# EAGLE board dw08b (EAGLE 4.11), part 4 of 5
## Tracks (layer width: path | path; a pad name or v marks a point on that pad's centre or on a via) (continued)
P_AC02  (via drill 0.61) (continued)
  Bottom 0.305: v95,52.07 93.47,52.07 93.22,52.32 91.19,52.32 B18.E1 | v95.25,48.01 99.31,48.01 99.57,47.75 100.33,47.75 100.58,48.01 102.11,48.01 103.38,49.28 105.66,49.28 B16.F2
P_AC03  (via drill 0.61)
  Top 0.305: v88.65,65.53 88.65,63.5 88.9,63.25 88.9,60.2 88.65,59.94 88.65,57.15 88.9,56.9 88.9,53.85 87.88,52.83 87.88,51.56 90.42,49.02 90.42,46.74 B18.H1
  2 0.305: v88.65,65.53 88.65,67.82 78.23,78.23 78.23,79.25 41.15,116.33 40.39,116.33 A22.H1
  Bottom 0.305: B16.H2 108.97,45.97 105.66,45.97 104.39,44.7 95.25,44.7 93.98,45.97 91.19,45.97 B18.H1
P_AC04  (via drill 0.61)
  Top 0.305: v84.33,81.28 84.07,81.03 v84.07,70.87 | v104.14,48.01 105.66,48.01 105.66,47.5 106.43,46.74 106.43,43.43 B16.J2
  2 0.305: v84.07,70.87 84.07,68.58 88.65,64.01 88.65,63.5 88.9,63.25 88.9,60.2 88.39,59.69 88.65,59.44 88.65,58.67 90.42,56.9 91.95,56.9 92.46,57.4 92.71,57.15 95,57.15 v104.14,48.01
  15 0.305: v51.82,111.25 50.29,109.73 50.55,109.47 50.55,108.97 64.52,95 66.55,95 67.06,95.5 67.31,95.25 68.58,95.25 69.85,93.98 69.85,91.95 69.34,91.44 69.6,91.19 69.6,89.92 77.22,82.3 79.25,82.3 79.76,82.8 80.01,82.55 82.3,82.55 83.57,81.28 v84.33,81.28
  Bottom 0.305: B18.J1 87.63,42.16 92.46,42.16 93.22,41.4 100.33,41.4 100.58,41.66 101.09,41.66 102.36,42.93 105.66,42.93 B16.J2 | v51.82,111.25 42.42,111.25 40.89,112.78 37.08,112.78 A22.J1
P_AC05  (via drill 0.61)
  Top 0.305: v109.47,43.18 109.47,40.39 B16.K2
  15 0.305: v48.26,107.7 48.51,107.95 50.55,107.95 78.99,79.5 78.99,78.49 90.68,66.8 91.44,66.8 96.27,61.98 96.27,60.96 94.49,59.18 106.68,46.99 106.68,45.97 v109.47,43.18
  Bottom 0.305: B18.L1 87.88,36.58 89.92,36.58 91.19,37.85 91.95,37.85 92.2,38.1 95,38.1 95.25,37.85 98.3,37.85 98.55,38.1 101.35,38.1 101.6,37.85 104.65,37.85 106.43,39.62 108.97,39.62 B16.K2 | v48.26,107.7 44.45,107.7 44.2,107.95 41.4,107.95 41.15,107.7 37.85,107.7 A22.L1
P_AC06  (via drill 0.61)
  Top 0.305: v66.04,80.01 66.04,78.49 66.29,78.23 66.29,73.15 66.04,72.9 66.04,69.6 67.06,68.58 67.06,62.48 66.55,61.98 v66.55,61.72
  2 0.305: v41.4,103.12 41.66,103.12 60.96,83.82 60.96,83.57 61.98,82.55 63.25,82.55 65.02,80.77 65.28,80.77 v66.04,80.01
  15 0.305: v66.55,61.72 80.52,47.75 80.52,45.47 78.99,43.94 78.99,42.42 88.14,33.27 v88.9,33.27
  Bottom 0.305: B16.L2 105.66,36.58 103.38,36.58 102.11,35.31 100.58,35.31 100.33,35.05 95.5,35.05 95,34.54 91.44,34.54 90.93,34.04 B18.M1 89.92,33.27 v88.9,33.27 | v41.4,103.12 40.39,103.12 A22.M1
P_AC07  (via drill 0.61)
  Top 0.305: v90.68,31.5 90.68,29.97 90.42,29.72 90.42,27.69 B18.P1 | v39.62,95.25 39.62,96.27 A22.P1 | v62.23,72.9 62.23,69.6 62.48,69.34 62.48,63.75 v62.23,63.5
  2 0.305: v39.62,95.25 39.62,95 49.53,85.09 49.78,85.09 50.55,84.33 50.55,84.07 55.63,78.99 56.13,78.99 v62.23,72.9 | v59.18,63.25 59.18,61.98 69.09,52.07 69.09,51.82 69.6,51.31 69.6,51.05 89.41,31.24 90.42,31.24 v90.68,31.5
  Bottom 0.305: v90.68,31.5 91.95,31.5 92.2,31.75 95,31.75 95.25,31.5 98.3,31.5 98.55,31.75 101.35,31.75 101.6,31.5 104.65,31.5 106.43,33.27 108.97,33.27 B16.M2 | v62.23,63.5 60.2,63.5 59.94,63.25 v59.18,63.25
P_AC08  (via drill 0.61)
  Top 0.305: v90.68,25.15 90.68,23.62 90.42,23.37 90.42,21.34 B18.S1 | v106.17,25.4 106.17,26.92 106.43,27.18 106.43,29.46 B16.N2 | v64.52,54.1 63.25,52.83 63.25,50.8 63.5,50.55 63.5,47.5 63.25,47.24 v63.25,46.23
  2 0.305: v63.25,46.23 63.25,45.72 77.47,31.5 v77.98,31.5 | v84.07,31.5 84.07,30.99 88.9,26.16 89.41,26.16 90.42,25.15 v90.68,25.15
  15 0.305: v64.52,54.1 64.52,55.37 51.56,68.33 51.56,70.36 45.47,76.45 45.47,82.8 39.12,89.15 39.12,89.92 A22.S1
  Bottom 0.305: v90.68,25.15 91.95,25.15 92.2,25.4 95,25.4 95.25,25.15 98.3,25.15 98.55,25.4 101.35,25.4 101.6,25.15 104.65,25.15 104.9,25.4 v106.17,25.4 | v77.98,31.5 79.25,31.5 79.5,31.75 82.3,31.75 82.55,31.5 v84.07,31.5
P_AC09  (via drill 0.61)
  Top 0.305: v25.4,124.46 25.4,123.7 25.15,123.44 25.15,120.65 25.4,120.4 25.4,117.35 25.15,117.09 25.15,114.3 25.4,114.05 25.4,111 25.15,110.74 25.15,107.95 25.4,107.7 25.4,104.65 25.15,104.39 25.15,101.6 25.4,101.35 v25.4,97.79
  2 0.305: v25.4,97.79 25.15,97.79 24.38,97.03 24.38,96.01 35.31,85.09 37.08,85.09 37.85,84.33 37.85,82.55 38.86,81.53 38.86,80.77 43.69,75.95 46.99,75.95 52.32,70.61 v52.58,70.61
  15 0.305: v105.16,27.43 93.98,38.61 93.98,39.12 88.65,44.45 88.65,45.97 80.52,54.1 80.52,54.86 B18.D2 | v55.88,70.61 56.39,70.61 60.45,66.55 60.45,62.99 59.69,62.23 65.02,56.9 66.55,56.9 67.06,57.4 67.31,57.15 69.6,57.15 v70.87,55.88
  Bottom 0.305: v105.16,27.43 105.41,27.18 106.43,27.18 106.68,26.92 108.97,26.92 B16.P2 | v25.4,124.46 29.46,124.46 29.72,124.71 A22.D2 | v52.58,70.61 v55.88,70.61 | v70.87,55.88 71.88,56.9 72.9,56.9 73.15,57.15 75.95,57.15 77.47,55.63 80.26,55.63 B18.D2
P_AC10  (via drill 0.61)
  Top 0.305: v101.6,23.62 101.6,25.15 101.35,25.4 101.35,28.45 101.6,28.7 101.6,31.5 101.35,31.75 101.35,34.8 101.6,35.05 101.6,37.85 100.58,38.86 v100.58,40.39 | v33.02,117.6 33.27,117.86 33.27,121.67 A22.E2 | v37.85,117.09 37.85,114.3 38.1,114.05 38.1,111 37.85,110.74 37.85,107.95 38.1,107.7 38.1,104.65 37.85,104.39 37.85,101.6 41.66,97.79 41.66,94.23 41.4,93.98 41.4,93.22 41.66,92.96 v41.66,91.44 | v83.57,47.75 84.07,48.26 84.07,51.82 B18.E2
  15 0.305: v100.58,40.39 v88.9,52.07 | v41.66,91.44 41.91,91.44 48.26,85.09 49.78,85.09 50.55,84.33 50.55,84.07 55.63,78.99 56.13,78.99 61.21,73.91 61.21,70.61 65.02,66.8 65.53,66.8 68.83,63.5 68.83,63.25 83.57,48.51 v83.57,47.75
  Bottom 0.305: v101.6,23.62 103.12,23.62 103.38,23.88 105.66,23.88 B16.R2 | v88.9,52.07 88.65,51.82 84.58,51.82 B18.E2 | v33.02,117.6 34.54,117.6 35.05,117.09 v37.85,117.09
P_AC11  (via drill 0.61)
  Top 0.305: v84.33,41.4 84.33,42.93 84.07,43.18 84.07,45.47 B18.H2 | v35.31,101.6 35.31,105.66 35.05,105.92 35.05,110.74 34.54,111.25 34.54,115.06 34.04,115.57 A22.H2
  15 0.305: v84.33,41.4 93.98,31.75 95,31.75 v106.17,20.57 | v35.31,101.6 36.83,101.6 58.42,80.01 58.42,79.25 63.5,74.17 64.01,74.17 66.04,72.14 66.04,67.31 69.6,63.75 69.6,63.5 84.58,48.51 84.58,46.74 B18.H2
  Bottom 0.305: v106.17,20.57 108.97,20.57 B16.S2
P_ACCEPT  (via drill 0.61)
  Top 0.305: v21.84,78.74 21.84,82.04 22.35,82.55 22.35,85.34 21.84,85.85 21.84,89.66 21.34,90.17 A23.S2 | v51.82,78.74 v51.82,75.95 | v133.1,76.2 133.1,63.5 133.35,63.25 133.35,60.2 133.1,59.94 133.1,57.15 133.35,56.9 133.35,53.85 133.1,53.59 133.1,50.8 133.35,50.55 133.35,47.5 133.1,47.24 133.1,44.45 133.35,44.2 133.35,41.15 132.08,39.88 132.08,39.37 131.83,39.12 131.83,37.08 B14.L2 | v127,19.05 126.75,19.3 126.75,22.1 127,22.35 127,25.15 126.75,25.4 126.75,28.45 127,28.7 127,31.5 126.75,31.75 126.75,34.8 127,35.05 v127,36.32
  Bottom 0.305: v21.84,78.74 v51.82,78.74 | v51.82,75.95 52.07,76.2 56.39,76.2 56.64,76.45 69.09,76.45 69.34,76.2 72.14,76.2 72.64,76.71 79.5,76.71 79.76,76.45 92.71,76.45 92.96,76.2 94.49,76.2 95,76.71 100.58,76.71 100.84,76.45 119.89,76.45 120.14,76.2 v133.1,76.2 | v127,19.05 123.95,19.05 122.43,17.53 119.63,17.53 B15.T2 | v127,36.32 128.52,36.32 128.78,36.58 131.06,36.58 B14.L2
P_ACCLR  (via drill 0.61)
  Top 0.305: v82.55,26.92 82.55,31.5 82.3,31.75 82.3,34.8 82.55,35.05 82.55,37.85 82.3,38.1 82.3,41.15 82.55,41.4 v82.55,44.2 | v93.47,44.45 93.47,45.97 93.73,46.23 93.73,48.51 B17.F2 | v33.27,92.2 33.27,96.27 A22.P2 | v44.45,71.37 v44.45,82.3 | v79.5,70.87 79.5,55.12 79.76,54.86 79.76,49.78 79.5,49.53 v79.5,46.99
  2 0.305: v44.45,82.3 v35.05,91.69 | v79.5,46.99 82.3,44.2 v82.55,44.2
  Bottom 0.305: v82.55,26.92 83.57,26.92 B18.P2 | v82.55,44.2 85.6,44.2 85.85,44.45 88.65,44.45 88.9,44.2 91.95,44.2 92.2,44.45 v93.47,44.45 | v33.27,92.2 34.54,92.2 v35.05,91.69 | v44.45,71.37 44.7,71.63 50.8,71.63 51.05,71.88 56.13,71.88 56.9,71.12 63.75,71.12 64.26,70.61 79.25,70.61 v79.5,70.87
P_ADD00  (via drill 0.61)
  Top 0.305: v69.6,72.14 69.6,63.5 69.85,63.25 69.85,60.45 68.33,58.93 68.33,56.13 B19.D2 | v98.3,72.39 98.04,72.64 98.04,82.3 98.55,82.8 98.55,83.82 98.81,84.07 98.81,86.61 98.55,86.87 v98.55,90.42 | v23.88,130.05 23.88,131.06 A23.B1 | v53.85,99.82 54.36,99.31 54.36,94.23 54.1,93.98 54.1,82.55 53.59,82.04 v53.59,78.99 | v67.06,72.39 v67.06,78.99
  15 0.305: v23.88,130.05 23.88,129.79 27.69,125.98 27.69,125.48 53.34,99.82 v53.85,99.82
  Bottom 0.305: v98.3,72.39 91.69,72.39 91.44,72.64 78.49,72.64 78.23,72.9 73.91,72.9 73.41,72.39 69.85,72.39 v69.6,72.14 69.34,72.39 v67.06,72.39 | v98.55,90.42 102.62,90.42 A17.S1 | v53.59,78.99 56.13,78.99 56.39,78.74 66.8,78.74 v67.06,78.99
P_ADD01  (via drill 0.61)
  Top 0.305: v25.4,130.3 25.4,130.05 23.88,128.52 23.88,125.98 A23.D1 23.88,124.71 v23.88,123.44 | v41.15,130.3 40.89,130.56 40.89,133.1 v43.18,135.38 | v69.09,79.5 69.09,77.47 73.15,73.41 73.15,57.4 72.64,56.9 72.64,53.34 72.14,52.83 B19.E2
  2 0.305: v69.09,79.5 70.36,80.77 68.58,82.55 66.55,82.55 66.04,82.04 65.79,82.3 65.02,82.3 62.99,84.33 62.99,84.58 62.48,85.09 60.71,85.09 44.2,101.6 44.2,104.65 44.7,105.16 44.45,105.41 44.45,106.68 43.18,107.95 41.15,107.95 40.64,107.44 40.39,107.7 39.62,107.7 v23.88,123.44
  15 0.305: v43.18,135.38 46.99,139.19 47.24,138.94 50.55,138.94 54.36,142.75 72.39,142.75 84.33,130.81 84.33,130.56 v89.41,125.48
  Bottom 0.305: v25.4,130.3 27.94,130.3 28.45,129.79 31.5,129.79 32,130.3 34.29,130.3 34.8,129.79 37.85,129.79 38.35,130.3 v41.15,130.3 | v89.41,125.48 92.96,125.48 A17.D2
P_ADD02  (via drill 0.61)
  Top 0.305: v68.33,51.05 68.33,49.78 B19.F2 | v45.47,74.93 45.21,75.18 45.21,81.53 45.47,81.79 45.47,82.8 44.7,83.57 44.7,88.39 44.2,88.9 44.2,91.95 44.45,92.2 44.45,95 44.2,95.25 44.2,98.3 44.45,98.55 44.45,101.35 44.2,101.6 44.2,104.65 44.45,104.9 44.45,107.7 44.2,107.95 44.2,111 44.45,111.25 44.45,114.05 44.2,114.3 44.2,117.35 44.45,117.6 v44.45,120.9
  2 0.305: v68.33,51.05 68.33,51.82 57.15,62.99 57.15,63.25 v45.47,74.93
  Bottom 0.305: A17.E2 96.27,122.17 92.46,122.17 91.19,120.9 v44.45,120.9 31.75,120.9 30.48,122.17 27.69,122.17 A23.E1
P_ADD03  (via drill 0.61)
  Top 0.305: v75.95,46.23 75.95,47.5 76.2,47.75 76.2,50.55 75.95,50.8 75.95,53.85 76.2,54.1 76.2,56.9 75.95,57.15 75.95,59.18 76.96,60.2 76.96,62.48 77.22,62.74 77.22,63.75 75.95,65.02 75.95,78.99 76.2,79.25 76.2,82.3 75.95,82.55 75.95,85.6 76.2,85.85 76.2,88.65 75.95,88.9 75.95,91.95 76.2,92.2 76.2,95 75.95,95.25 75.95,98.3 76.2,98.55 76.2,101.35 75.95,101.6 75.95,104.65 76.2,104.9 76.2,107.7 75.95,107.95 75.95,111 76.2,111.25 v76.2,114.55
  Bottom 0.305: A17.H2 96.27,115.82 92.46,115.82 91.19,114.55 v76.2,114.55 31.75,114.55 30.48,115.82 27.69,115.82 A23.H1 | v75.95,46.23 74.42,46.23 74.17,45.97 72.14,45.97 B19.H2
P_ADD04  (via drill 0.61)  (1 unrouted)
  Top 0.305: v60.45,52.32 60.45,66.55 59.94,67.06 59.94,70.1 58.42,71.63 58.42,72.64 58.67,72.9 58.67,78.99 57.15,80.52 57.15,82.3 56.9,82.55 56.9,85.6 57.15,85.85 57.15,88.65 56.9,88.9 56.9,91.95 57.15,92.2 v57.15,93.47
  15 0.305: v60.45,52.32 60.96,52.32 68.83,44.45 68.83,43.43 B19.J2 | v57.15,93.47 57.15,93.98 39.88,111.25 v39.37,111.25
  Bottom 0.305: v39.37,111.25 29.72,111.25 28.19,112.78 24.38,112.78 A23.J1
P_ADD05  (via drill 0.61)  (1 unrouted)
  Top 0.305: v71.12,43.18 71.37,42.93 71.37,40.39 B19.K2 | v21.84,93.98 21.84,94.74 22.61,95.5 22.61,99.31 22.35,99.57 22.35,100.33 22.61,100.58 22.61,102.11 23.88,103.38 23.88,105.66 A23.L1
  15 0.305: v71.12,43.18 46.99,67.31 46.99,67.56 44.7,69.85 42.42,69.85 35.56,76.71 35.56,78.23 21.84,91.95 v21.84,93.98
P_ADD06  (via drill 0.61)
  Top 0.305: v50.55,39.62 50.55,38.1 50.8,37.85 v50.8,35.31 | v28.19,71.88 28.19,82.04 28.7,82.55 28.7,93.98 28.96,94.23 28.96,97.79 28.19,98.55 28.19,102.36 27.69,102.87 A23.M1 | v31.5,71.88 31.5,63.5 31.75,63.25 31.75,60.2 31.5,59.94 31.5,57.15 31.75,56.9 31.75,53.85 31.5,53.59 31.5,50.8 31.75,50.55 31.75,47.5 31.5,47.24 31.5,44.45 31.75,44.2 v31.75,41.66
  Bottom 0.305: v50.55,39.62 46.74,39.62 B21.K2 45.47,39.62 42.67,39.62 40.89,41.4 36.07,41.4 35.81,41.66 v31.75,41.66 | v50.8,35.31 54.86,35.31 55.12,35.05 62.23,35.05 62.48,35.31 64.01,35.31 65.28,36.58 67.56,36.58 B19.L2 | v31.5,71.88 v28.19,71.88
P_ADD07  (via drill 0.61)
  Top 0.305: v26.92,95.25 26.92,96.27 A23.P1 | v38.1,95.25 38.1,91.95 37.85,91.69 37.85,88.9 38.1,88.65 38.1,85.6 37.85,85.34 37.85,82.55 38.1,82.3 38.1,66.8 37.85,66.55 37.85,63.5 38.1,63.25 38.1,60.2 37.85,59.94 37.85,57.15 38.1,56.9 38.1,53.85 37.85,53.59 37.85,50.8 38.1,50.55 38.1,47.5 37.85,47.24 37.85,44.45 38.1,44.2 38.1,41.15 37.85,40.89 37.85,38.1 38.1,37.85 v38.1,35.05
  Bottom 0.305: B19.M2 70.87,33.27 67.56,33.27 66.29,32 50.8,32 49.53,33.27 46.74,33.27 B21.M2 45.47,33.27 42.67,33.27 40.89,35.05 v38.1,35.05 | v26.92,95.25 31.5,95.25 31.75,95 34.8,95 35.05,95.25 v38.1,95.25
P_ADD08  (via drill 0.61)
  Top 0.305: v31.5,90.42 31.5,88.9 32,88.39 32,83.57 32.26,83.31 32.26,82.8 32.51,82.55 32.51,74.68 33.02,74.17 v33.02,72.14 | v56.9,72.64 56.9,63.5 57.15,63.25 57.15,60.2 56.9,59.94 56.9,57.15 57.15,56.9 57.15,53.85 56.9,53.59 56.9,50.8 57.15,50.55 57.15,47.5 56.9,47.24 56.9,44.45 57.15,44.2 57.15,41.15 56.9,40.89 56.9,38.1 57.15,37.85 57.15,34.8 56.9,34.54 56.9,31.75 57.15,31.5 v57.15,28.7
  Bottom 0.305: B21.P2 46.48,27.69 46.99,28.19 50.55,28.19 51.05,28.7 v57.15,28.7 62.23,28.7 62.48,28.96 64.01,28.96 65.28,30.23 67.56,30.23 B19.N2 | v31.5,90.42 27.69,90.42 A23.S1 | v33.02,72.14 33.27,72.39 50.55,72.39 50.8,72.64 v56.9,72.64
P_ADD09  (via drill 0.61)
  Top 0.305: v46.23,25.4 46.23,23.62 45.97,23.37 45.97,21.34 B21.S2 | v17.78,120.65 17.53,120.9 17.53,124.71 A23.D2 | v22.86,110.74 22.61,110.49 22.61,106.93 22.35,106.68 22.35,102.87 21.84,102.36 21.84,100.84 21.59,100.58 21.59,100.08 v20.07,98.55 | v8.89,92.2 v8.89,95.25 | v20.83,80.01 20.83,75.69 21.08,75.44 v21.08,67.56 | v25.15,67.56 25.15,63.5 25.4,63.25 25.4,60.2 25.15,59.94 25.15,57.15 25.4,56.9 25.4,53.85 25.15,53.59 25.15,50.8 25.4,50.55 25.4,47.5 25.15,47.24 25.15,44.45 25.4,44.2 25.4,41.15 25.15,40.89 25.15,38.1 25.4,37.85 25.4,34.8 25.15,34.54 25.15,31.75 25.4,31.5 25.4,28.45 25.15,28.19 v25.15,25.4
  2 0.305: v8.89,92.2 9.4,92.2 18.8,82.8 18.8,82.55 19.05,82.3 19.05,81.79 v20.83,80.01
  15 0.305: v26.67,111.76 v17.78,120.65
  Bottom 0.305: B19.P2 70.87,26.92 68.33,26.92 66.55,25.15 63.5,25.15 63.25,25.4 60.45,25.4 60.2,25.15 57.15,25.15 56.9,25.4 54.1,25.4 53.85,25.15 50.8,25.15 50.55,25.4 47.75,25.4 47.5,25.15 46.48,25.15 v46.23,25.4 45.97,25.15 44.45,25.15 44.2,25.4 41.4,25.4 41.15,25.15 38.1,25.15 37.85,25.4 35.05,25.4 34.8,25.15 31.75,25.15 31.5,25.4 28.7,25.4 28.45,25.15 25.4,25.15 v25.15,25.4 | v26.67,111.76 26.16,111.25 25.4,111.25 24.89,110.74 v22.86,110.74 | v20.07,98.55 19.05,98.55 15.49,95 12.7,95 12.45,95.25 v8.89,95.25 | v21.08,67.56 21.34,67.82 24.89,67.82 v25.15,67.56
P_ADD10  (via drill 0.61)
  Top 0.305: v68.33,19.05 68.33,23.11 B19.R2 | v20.57,120.65 20.57,121.67 A23.E2 | v11.43,114.3 v11.43,117.09 | v8.13,111.25 v8.13,114.05 | v12.45,103.12 12.45,101.6 12.7,101.35 v12.7,98.04 | v22.35,75.95 21.84,75.44 21.84,68.33 22.35,67.82 v22.35,51.82 | v44.45,31.5 44.45,28.45 44.2,28.19 44.2,25.4 44.45,25.15 44.45,22.1 42.93,20.57 42.93,18.03 B21.T2
  2 0.305: v8.13,111.25 9.65,109.73 9.65,107.95 8.89,107.19 9.14,106.93 9.14,106.43 v12.45,103.12 | v44.45,31.5 v24.13,51.82
  15 0.305: v20.57,120.65 20.57,120.4 v23.62,117.35 | v12.7,98.04 12.45,98.04 11.68,97.28 11.68,96.01 19.05,88.65 19.05,85.6 18.54,85.09 18.8,84.84 18.8,82.55 19.05,82.3 19.05,79.25 v22.35,75.95
  Bottom 0.305: v68.33,19.05 66.8,19.05 66.55,18.8 63.5,18.8 63.25,19.05 60.45,19.05 60.2,18.8 57.15,18.8 56.9,19.05 54.1,19.05 53.85,18.8 50.8,18.8 50.55,19.05 47.75,19.05 46.23,17.53 43.43,17.53 B21.T2 | v23.62,117.35 23.11,117.86 18.03,117.86 17.78,117.6 12.7,117.6 12.19,117.09 v11.43,117.09 | v11.43,114.3 9.4,114.3 9.14,114.05 v8.13,114.05 | v24.13,51.82 v22.35,51.82
P_ADD11  (via drill 0.61)
  Top 0.305: v42.93,9.14 42.93,10.41 B21.V2 | v69.85,9.14 69.85,12.45 69.6,12.7 69.6,15.75 71.37,17.53 71.37,20.07 B19.S2 | v20.57,111.25 20.57,115.32 A23.H2 | v13.72,80.77 13.97,80.52 13.97,72.14 13.72,71.88 13.72,69.09 12.45,67.82 12.45,63.5 12.7,63.25 12.7,60.2 12.45,59.94 12.45,57.15 12.7,56.9 12.7,53.85 12.45,53.59 12.45,50.8 12.7,50.55 12.7,47.5 12.45,47.24 12.45,44.45 12.7,44.2 12.7,41.15 12.45,40.89 12.45,38.1 12.7,37.85 12.7,34.8 12.45,34.54 12.45,31.75 12.7,31.5 12.7,28.45 12.45,28.19 12.45,25.4 12.7,25.15 12.7,22.1 12.45,21.84 12.45,19.05 12.7,18.8 12.7,15.75 12.45,15.49 12.45,12.7 12.7,12.45 v12.7,7.11
  2 0.305: v11.43,110.49 14.48,107.44 14.73,107.44 15.49,106.68 15.49,106.17 18.8,102.87 18.8,101.6 23.62,96.77 23.62,95.76 26.42,92.96 v26.42,92.2
  Bottom 0.305: v69.85,9.14 v42.93,9.14 42.67,8.89 34.54,8.89 32.77,7.11 31.5,7.11 31.24,6.86 12.95,6.86 v12.7,7.11 | v20.57,111.25 12.7,111.25 11.94,110.49 v11.43,110.49 | v26.42,92.2 25.65,92.2 15.49,82.04 15.49,80.77 v13.72,80.77
P_BAC00  (via drill 0.61)
  15 0.305: v66.55,131.57 66.29,131.32 76.45,121.16 76.96,121.16 77.72,120.4 77.72,119.13 77.47,118.87 77.47,117.86 77.98,117.35 78.23,117.35 81.28,114.3 82.3,114.3 92.46,104.14 92.71,104.14 114.05,82.8 114.05,82.55 117.09,79.5 117.09,76.45 123.19,70.36 123.19,68.58 134.87,56.9 v135.38,56.9
  Bottom 0.305: B12.D2 156.46,55.63 152.65,55.63 151.38,56.9 v135.38,56.9 130.05,56.9 128.78,55.63 125.98,55.63 B15.D1 | v66.55,131.57 66.29,131.83 62.48,131.83 A20.B1
P_BAC01  (via drill 0.61)
  Top 0.305: v156.97,44.45 156.97,45.97 157.23,46.23 157.23,48.51 B12.F2 | v128.52,56.9 128.52,53.09 B15.E1
  2 0.305: v66.04,124.71 75.18,115.57 75.18,114.05 77.98,111.25 79.25,111.25 80.01,110.49 80.26,110.49 85.34,105.41 85.34,105.16 87.88,102.62 87.88,102.36 92.46,97.79 92.71,97.79 107.7,82.8 107.7,82.55 110.74,79.5 110.74,78.49 120.4,68.83 120.4,65.02 v128.52,56.9
  15 0.305: v130.81,53.09 v138.43,45.47
  Bottom 0.305: v130.81,53.09 129.03,53.09 B15.E1 | v138.43,45.47 138.68,45.21 139.7,45.21 140.72,44.2 142.75,44.2 143,44.45 145.8,44.45 146.05,44.2 149.1,44.2 149.35,44.45 152.15,44.45 152.4,44.2 155.45,44.2 155.7,44.45 v156.97,44.45 | v66.04,124.71 65.79,124.46 62.48,124.46 62.23,124.71 A20.D1
P_BAC02  (via drill 0.61)
  Top 0.305: v152.15,47.24 152.15,44.45 152.4,44.2 v152.4,42.93 | v134.87,62.23 135.13,61.98 135.13,60.45 136.65,58.93 136.65,50.8 136.14,50.29 v136.14,49.28
  2 0.305: v78.49,118.36 114.05,82.8 114.05,82.55 117.09,79.5 117.09,78.99 124.97,71.12 125.98,71.12 v134.87,62.23
  15 0.305: v67.06,122.17 68.07,122.17 73.15,117.09 74.93,117.09 v76.2,118.36
  Bottom 0.305: 136.14,47.75 148.84,47.75 149.35,47.24 v152.15,47.24 | 136.14,47.75 133.6,47.75 133.1,47.24 129.54,47.24 129.03,46.74 B15.H1 | v152.4,42.93 156.46,42.93 B12.J2 | v67.06,122.17 65.79,122.17 A20.E1 | v78.49,118.36 v76.2,118.36 | 136.14,47.75 v136.14,49.28
P_BAC03  (via drill 0.61)
  Top 0.305: v152.15,40.89 152.15,38.1 152.4,37.85 v152.4,36.58 | v65.79,112.27 65.79,115.57 A20.H1
  2 0.305: v65.79,112.27 68.58,109.47 68.58,109.22 71.12,106.68 71.37,106.68 86.87,91.19 88.14,91.19 88.65,90.68 88.65,89.41 107.7,70.36 107.7,63.5 125.98,45.21 125.98,43.43 B15.J1
  Bottom 0.305: v152.15,40.89 149.35,40.89 148.84,41.4 131.32,41.4 130.56,42.16 125.73,42.16 B15.J1 | v152.4,36.58 156.46,36.58 B12.L2
P_BAC04  (via drill 0.61)
  Top 0.305: v155.19,37.85 155.19,35.05 157.23,33.02 157.23,30.73 B12.N2 | v85.09,94.49 83.31,92.71 83.31,91.69 82.8,91.19 82.8,89.92 84.33,88.39 84.33,86.36 84.84,85.85 85.34,85.85 88.9,82.3 91.69,82.3 92.2,82.8 v92.2,88.14 | v125.48,39.37 125.48,37.08 B15.L1
  2 0.305: v129.79,55.12 130.56,54.36 131.06,54.36 131.83,53.59 131.83,52.58 127.25,48.01 126.75,48.01 126.24,47.5 126.24,45.97 126.75,45.47 126.75,43.43 127,43.18 127,42.42 125.48,40.89 v125.48,39.37
  15 0.305: v64.26,112.27 65.28,111.25 66.55,111.25 67.06,110.74 67.31,110.74 68.58,109.47 68.58,109.22 71.12,106.68 71.37,106.68 75.69,102.36 76.2,102.36 84.07,94.49 v85.09,94.49 | v92.2,88.14 93.73,89.66 93.98,89.41 96.01,89.41 100.33,85.09 100.58,85.09 101.35,84.33 101.35,83.06 113.03,71.37 113.03,70.36 117.6,65.79 117.6,64.01 118.11,63.5 119.38,63.5 120.65,62.23 120.4,61.98 120.4,60.96 120.9,60.45 123.19,60.45 126.49,57.15 126.75,57.15 128.78,55.12 v129.79,55.12
  Bottom 0.305: v155.19,37.85 152.4,37.85 152.15,38.1 149.1,38.1 148.84,37.85 146.05,37.85 145.8,38.1 142.75,38.1 142.49,37.85 139.7,37.85 139.45,38.1 136.4,38.1 136.14,37.85 133.35,37.85 133.1,38.1 130.3,38.1 129.54,37.34 126.24,37.34 B15.L1 | v64.26,112.27 62.48,112.27 A20.J1
P_BAC05  (via drill 0.61)
  Top 0.305: v128.52,31.75 128.52,32.77 B15.M1 128.52,34.04 128.52,36.32 126.75,38.1 v126.75,39.62 | v152.15,31.75 152.4,31.5 152.4,28.45 152.15,28.19 152.15,25.4 152.4,25.15 v152.4,23.88 | v61.98,102.87 61.98,105.66 A20.L1
  2 0.305: v61.98,102.87 65.28,99.57 65.28,99.06 67.31,97.03 67.31,96.01 68.07,95.25 69.6,95.25 79.5,85.34 82.55,85.34 83.31,86.11 83.57,85.85 84.33,85.85 v89.15,81.03
  15 0.305: v91.95,80.77 93.73,78.99 94.49,78.99 101.6,71.88 101.6,69.85 104.9,66.55 105.41,66.55 107.7,64.26 107.7,63.5 117.6,53.59 117.6,50.8 116.84,50.04 117.09,49.78 117.09,49.28 v126.75,39.62
  Bottom 0.305: v128.52,31.75 133.1,31.75 133.35,31.5 136.4,31.5 136.65,31.75 139.45,31.75 139.7,31.5 142.75,31.5 143,31.75 145.8,31.75 146.05,31.5 149.1,31.5 149.35,31.75 v152.15,31.75 | v152.4,23.88 156.46,23.88 B12.R2 | v89.15,81.03 89.41,80.77 v91.95,80.77
P_BAC06  (via drill 0.61)
  Top 0.305: v142.49,28.7 142.49,31.5 143,32 143,49.53 143.26,49.78 143.26,51.31 144.53,52.58 144.53,54.86 B13.D2 | v139.45,53.09 139.45,53.85 139.7,54.1 v139.7,55.63
  15 0.305: v110.74,71.63 103.12,79.25 101.09,79.25 100.84,78.99 99.82,78.99 88.65,90.17 88.65,90.68 88.14,91.19 86.36,91.19 75.95,101.6 73.66,101.6 73.41,101.85 72.9,101.35 69.85,101.35 69.6,101.6 67.31,101.6 65.79,103.12 A20.M1 | v116.08,71.63 118.87,71.63 122.43,68.07 122.68,68.07 v137.67,53.09
  Bottom 0.305: v142.49,28.7 133.6,28.7 133.1,28.19 129.54,28.19 129.03,27.69 B15.P1 | v110.74,71.63 111,71.88 115.82,71.88 v116.08,71.63 | v139.45,53.09 v137.67,53.09 | v139.7,55.63 143.76,55.63 B13.D2
P_BAC07  (via drill 0.61)
  Top 0.305: v139.7,22.35 139.7,25.15 139.45,25.4 139.45,28.45 139.7,28.7 139.7,31.5 139.45,31.75 139.45,34.8 139.7,35.05 139.7,37.85 139.45,38.1 v139.45,39.88 139.45,41.15 139.7,41.4 139.7,44.2 139.45,44.45 139.45,47.5 139.7,47.75 v139.7,49.28 | v82.3,84.33 82.3,85.6 82.55,85.85 v82.55,86.87 | v85.34,86.87 85.34,88.65 85.85,89.15 v85.85,90.17
  15 0.305: v80.52,84.33 v68.33,96.52 | v87.63,90.17 105.92,71.88 106.93,71.88 113.28,65.53 113.54,65.53 115.82,63.25 117.09,63.25 117.6,62.74 117.6,61.47 125.98,53.09 126.24,53.09 126.75,52.58 126.75,52.07 138.94,39.88 v139.45,39.88
  Bottom 0.305: v139.7,22.35 133.6,22.35 133.1,21.84 129.54,21.84 129.03,21.34 B15.S1 | v139.7,49.28 143.76,49.28 B13.F2 | v68.33,96.52 68.07,96.77 65.79,96.77 A20.P1 | v82.3,84.33 v80.52,84.33 | v85.34,86.87 v82.55,86.87 | v87.63,90.17 v85.85,90.17
P_BAC08  (via drill 0.61)
  Top 0.305: v63.5,73.15 63.5,82.3 63.25,82.55 63.25,85.34 65.02,87.12 65.02,89.92 A20.S1 | v117.6,73.15 117.6,61.47 119.13,59.94 119.13,56.13 B15.D2
  15 0.305: v129.29,44.2 128.52,44.2 120.4,52.32 120.4,53.85 119.38,54.86 B15.D2
  Bottom 0.305: v63.5,73.15 63.75,73.41 68.07,73.41 68.33,73.15 73.15,73.15 73.66,73.66 78.49,73.66 78.74,73.41 91.69,73.41 91.95,73.15 95.5,73.15 96.01,73.66 99.57,73.66 99.82,73.41 117.35,73.41 v117.6,73.15 | v129.29,44.2 129.79,44.2 130.05,44.45 133.1,44.45 133.35,44.2 136.14,44.2 136.4,44.45 139.45,44.45 140.97,42.93 143.76,42.93 B13.J2
P_BAC09  (via drill 0.61)
  Top 0.305: v57.15,131.32 57.15,130.3 55.63,128.78 55.63,125.98 A20.D2 | v59.94,131.32 59.94,133.1 60.45,133.6 v60.45,134.11 | v78.99,119.89 78.99,119.38 79.5,118.87 79.5,114.3 78.99,113.79 v78.99,112.27 | v111,80.77 111.51,80.26 111.51,72.39 112.01,71.88 v112.01,70.87
  2 0.305: v112.01,70.87 112.52,70.87 116.59,66.8 117.86,66.8 119.63,65.02 119.63,64.77 126.75,57.66 126.75,57.15 127,56.9 127,53.85 125.98,52.83 125.98,52.32 v125.73,52.07
  15 0.305: v125.73,52.07 v141.22,36.58 | v76.71,119.89 v62.48,134.11 | v78.99,112.27 78.99,111.76 85.34,105.41 85.34,105.16 87.88,102.62 87.88,102.36 92.46,97.79 92.71,97.79 109.73,80.77 v111,80.77
  Bottom 0.305: v125.73,52.07 125.22,52.07 124.97,52.32 122.94,52.32 B15.E2 | v141.22,36.58 143.76,36.58 B13.L2 | v59.94,131.32 v57.15,131.32 | v62.48,134.11 v60.45,134.11 | v78.99,119.89 v76.71,119.89
P_BAC10  (via drill 0.61)
  Top 0.305: v58.17,125.73 58.17,122.68 A20.E2 | v85.85,109.22 85.85,110.74 85.34,111.25 v85.34,113.03 | v143.26,73.91 143.26,62.48 143,62.23 v143,52.58 | v145.8,45.97 145.8,44.45 147.83,42.42 147.83,41.91 149.35,40.39 149.35,38.1 148.84,37.59 v148.84,36.83 | v146.05,36.83 146.05,34.8 144.53,33.27 144.53,30.73 B13.N2
  2 0.305: v72.64,119.63 72.64,119.13 74.68,117.09 76.45,117.09 77.22,117.86 77.47,117.6 77.72,117.6 77.98,117.35 78.49,117.35 85.85,109.98 v85.85,109.22 | v143,52.58 143,48.77 v145.8,45.97
  15 0.305: v140.97,30.23 124.71,46.48 122.94,46.48 B15.H2 | v58.17,125.73 59.69,125.73 61.98,123.44 63.25,123.44 64.01,124.21 64.26,123.95 65.28,123.95 66.04,123.19 68.07,123.19 71.63,119.63 v72.64,119.63 | v85.34,113.03 85.34,112.27 92.71,104.9 92.96,104.9 115.57,82.3 v115.82,82.3 | v119.38,82.55 119.89,82.55 v128.02,74.42
  Bottom 0.305: v140.97,30.23 143.76,30.23 B13.N2 | v115.82,82.3 117.35,82.3 117.6,82.55 v119.38,82.55 | v128.02,74.42 128.27,74.17 137.41,74.17 137.92,73.66 143,73.66 v143.26,73.91 | v146.05,36.83 v148.84,36.83
P_BAC11  (via drill 0.61)
  Top 0.305: v122.94,35.81 122.94,39.37 B15.K2 | v54.1,115.82 54.36,115.57 54.36,113.28 54.1,113.03 54.1,112.27 54.36,112.01 54.36,106.93 54.1,106.68 54.1,105.92 54.36,105.66 54.36,101.6 v54.1,101.35 | v47.75,101.6 47.75,99.57 48.01,99.31 48.01,94.23 47.75,93.98 47.75,93.22 48.01,92.96 48.01,89.15 45.97,87.12 v45.97,85.85 | v59.94,49.53 59.94,47.75 60.45,47.24 60.45,12.7 59.94,12.19 v59.94,2.79 | v109.73,3.56 v109.73,12.45 | v133.1,12.7 133.1,15.75 133.35,16 133.35,18.8 133.1,19.05 133.1,22.1 133.35,22.35 133.35,24.89 v133.6,25.15
  15 0.305: v133.6,25.15 v122.94,35.81 | v29.72,82.55 28.19,81.03 30.48,78.74 31.5,78.74 34.8,75.44 34.8,74.42 59.69,49.53 v59.94,49.53
  Bottom 0.305: v133.6,25.15 136.4,25.15 136.65,25.4 139.45,25.4 139.7,25.15 140.21,25.15 140.46,24.89 143.51,24.89 144.02,24.38 B13.R2 | v54.1,115.82 58.17,115.82 A20.H2 | v54.1,101.35 50.8,101.35 50.55,101.6 v47.75,101.6 | v45.97,85.85 38.1,85.85 37.59,85.34 34.04,85.34 33.78,85.6 32.77,85.6 v29.72,82.55 | v59.94,2.79 60.2,2.54 94.23,2.54 95.5,3.81 109.47,3.81 v109.73,3.56 | v109.73,12.45 111,12.45 111.25,12.7 114.05,12.7 114.3,12.45 117.35,12.45 117.6,12.7 120.4,12.7 120.65,12.45 123.7,12.45 123.95,12.7 126.75,12.7 127,12.45 130.05,12.45 130.3,12.7 v133.1,12.7
P_BREAK  (via drill 0.61)
  Top 0.305: v25.4,96.52 25.15,96.27 25.15,95.25 25.4,95 25.4,91.95 25.15,91.69 25.15,88.9 25.4,88.65 25.4,85.6 25.15,85.34 25.15,82.55 25.4,82.3 v25.4,72.9 | v123.95,73.66 123.95,48.77 124.21,48.51 v124.21,44.45 123.95,44.2 123.95,29.72 124.21,29.46 124.21,25.65 123.44,24.89 123.44,21.59 122.94,21.08 B15.S2
  Bottom 0.305: v25.4,96.52 23.62,96.52 23.37,96.77 21.34,96.77 A23.P2 | v25.4,72.9 32.26,72.9 32.51,73.15 50.29,73.15 50.55,73.41 52.83,73.41 53.34,73.91 57.15,73.91 57.4,74.17 68.33,74.17 68.58,73.91 72.9,73.91 73.41,74.42 78.74,74.42 78.99,74.17 91.95,74.17 92.2,73.91 95.25,73.91 95.76,74.42 99.82,74.42 100.08,74.17 119.13,74.17 119.38,73.91 123.7,73.91 v123.95,73.66 | v124.21,44.45 126.75,44.45 128.02,43.18 128.52,43.18 128.78,42.93 131.06,42.93 B14.J2
P_BRKRQ  (via drill 0.61)
  Top 0.305: v22.35,137.92 22.35,114.55 21.84,114.05 21.84,110.49 21.34,109.98 A23.K2 | v100.08,138.43 100.08,132.33 A17.B1 | v95.25,55.12 95.25,56.9 95,57.15 95,59.69 v97.54,62.23 | v73.15,90.17 73.15,93.98 73.41,94.23 73.41,97.79 73.66,98.04 73.66,99.06 73.15,99.57 73.15,112.01 v72.9,112.27 | v69.6,115.57 69.6,117.35 69.85,117.6 69.85,120.4 69.6,120.65 69.6,123.7 69.85,123.95 69.85,126.75 69.6,127 69.6,130.05 73.66,134.11 v73.66,138.68
  2 0.305: v95.25,55.12 95.25,54.61 95.5,54.36 93.98,52.83 93.98,51.56 96.27,49.28 96.27,47.5 95,46.23 95,44.45 94.23,43.69 94.23,43.43 B17.J2 | v97.54,62.23 97.54,62.99 99.06,64.52 98.55,65.02 98.55,66.8 86.61,78.74 85.34,78.74 80.77,83.31 80.01,83.31 79.5,83.82 79.5,84.33 73.66,90.17 v73.15,90.17 | v69.6,115.57 v72.9,112.27
  Bottom 0.305: v22.35,137.92 43.43,137.92 43.69,138.18 48.51,138.18 48.77,138.43 55.12,138.43 55.63,138.94 73.66,138.94 | 73.66,138.94 90.42,138.94 90.93,138.43 97.03,138.43 97.28,138.18 99.82,138.18 v100.08,138.43 | 73.66,138.94 v73.66,138.68
P_CAINCR  (via drill 0.61)
  Top 0.305: v9.65,142.49 9.65,114.55 9.14,114.05 9.14,111.25 9.4,111 9.4,107.7 9.14,107.44 9.14,107.19 8.89,106.93 8.89,103.89 8.64,103.63 A24.M2 | v49.28,142.49 49.53,142.24 49.53,141.99 49.78,141.73 49.78,136.91 v49.53,136.65 | v69.09,137.16 69.6,136.65 v69.6,134.11 | v69.85,49.02 69.85,50.55 69.6,50.8 69.6,53.85 69.85,54.1 69.85,56.9 69.6,57.15 69.6,59.18 70.61,60.2 70.61,62.48 v71.37,63.25 | v74.93,63.5 74.93,64.77 75.18,65.02 75.18,71.37 v74.93,71.63 | v78.23,71.63 78.99,72.39 78.99,82.3 79.5,82.8 v79.5,107.19 | v83.57,105.66 83.31,105.92 83.31,107.95 82.3,108.97 82.3,111 82.55,111.25 82.55,114.05 82.3,114.3 82.3,117.35 82.55,117.6 82.55,120.4 82.3,120.65 v82.3,122.17
  2 0.305: v79.5,107.19 80.52,108.2 80.77,107.95 81.28,107.95 v83.57,105.66
  15 0.305: v69.6,134.11 72.64,131.06 73.41,131.06 v82.3,122.17 v90.93,113.54 | v88.9,29.97 88.9,30.48 70.36,49.02 v69.85,49.02
  Bottom 0.305: v9.65,142.49 9.91,142.75 41.91,142.75 42.42,142.24 49.02,142.24 v49.28,142.49 | v49.53,136.65 49.78,136.91 55.63,136.91 56.13,137.41 68.83,137.41 v69.09,137.16 | v90.93,113.54 91.19,113.79 91.44,113.79 91.95,114.3 95,114.3 96.52,112.78 99.31,112.78 A17.J1 | v88.9,29.97 89.15,30.23 92.96,30.23 B17.N2 | v71.37,63.25 72.9,63.25 73.15,63.5 v74.93,63.5 | v78.23,71.63 v74.93,71.63
P_DATA00  (via drill 0.61)
  Top 0.305: v50.8,55.88 50.8,56.9 49.53,58.17 49.53,58.67 49.28,58.93 49.28,61.21 B21.B1 49.28,62.48 49.28,69.6 v48.77,70.1 | v6.35,131.83 6.35,130.05 6.1,129.79 6.1,127 6.35,126.75 6.35,123.7 6.1,123.44 6.1,120.65 6.35,120.4 6.35,117.35 6.1,117.09 6.1,114.3 6.35,114.05 6.35,111 6.1,110.74 6.1,107.95 6.35,107.7 6.35,104.65 6.1,104.39 6.1,101.6 6.35,101.35 6.35,98.3 6.1,98.04 6.1,95.25 6.35,95 6.35,91.95 6.1,91.69 6.1,88.9 6.35,88.65 6.35,85.6 6.1,85.34 6.1,82.55 6.35,82.3 v6.35,70.36
  Bottom 0.305: v50.8,55.88 52.32,55.88 52.58,55.63 54.86,55.63 B20.D2 | v6.35,131.83 10.41,131.83 A24.B1 | v6.35,70.36 9.65,70.36 9.91,70.1 37.85,70.1 38.1,69.85 48.51,69.85 v48.77,70.1
P_DATA01  (via drill 0.61)
  Top 0.305: v11.18,120.65 11.18,124.71 A24.D1 | v15.49,120.4 15.49,117.6 16.26,116.84 16.26,113.28 16,113.03 16,112.27 16.26,112.01 16.26,106.93 16,106.68 16,105.92 16.26,105.66 16.26,100.58 16,100.33 16,99.57 16.26,99.31 16.26,94.23 16,93.98 16,82.55 15.49,82.04 v15.49,71.12 | v43.18,70.87 44.2,69.85 44.2,63.5 44.45,63.25 44.45,60.2 44.2,59.94 44.2,57.15 44.45,56.9 v44.45,56.39
  Bottom 0.305: B20.E2 58.17,52.32 55.63,52.32 53.09,54.86 49.53,54.86 B21.D1 48.51,55.63 46.23,55.63 45.97,55.88 44.96,55.88 v44.45,56.39 | v11.18,120.65 12.45,120.65 12.7,120.4 v15.49,120.4 | v15.49,71.12 15.75,70.87 38.1,70.87 38.35,70.61 42.93,70.61 v43.18,70.87
P_DATA02  (via drill 0.61)
  Top 0.305: v52.32,49.28 52.32,51.82 B21.E1 52.32,53.09 52.32,55.88 51.56,56.64 51.56,57.66 51.05,58.17 51.05,62.99 50.04,64.01 50.04,70.36 48.51,71.88 v48.51,76.2 | v18.8,121.92 18.8,120.65 19.05,120.4 19.05,117.35 18.8,117.09 18.8,114.3 19.05,114.05 19.05,111 18.8,110.74 18.8,107.95 19.05,107.7 19.05,104.65 18.8,104.39 18.8,101.6 19.05,101.35 19.05,98.3 18.8,98.04 18.8,95.76 v19.05,95.5
  2 0.305: v19.05,95.5 19.05,95.25 21.34,92.96 21.84,92.96 37.08,77.72 37.59,77.72 v39.12,76.2
  Bottom 0.305: v52.32,49.28 54.86,49.28 B20.F2 | v18.8,121.92 17.27,121.92 17.02,122.17 14.99,122.17 A24.E1 | v48.51,76.2 v39.12,76.2
P_DATA03  (via drill 0.61)
  Top 0.305: v14.99,113.28 14.99,115.57 A24.H1 | v46.48,82.04 47.24,81.28 47.24,75.95 47.75,75.44 v47.75,50.8 | v51.31,50.55 51.31,48.77 52.32,47.75 52.32,46.74 B21.H1
  2 0.305: v14.99,113.28 36.07,92.2 36.07,91.69 44.45,83.31 44.96,83.31 46.23,82.04 v46.48,82.04
  Bottom 0.305: B20.H2 58.17,45.97 53.09,45.97 B21.H1 | v47.75,50.8 50.55,50.8 50.8,50.55 v51.31,50.55
P_DATA04  (via drill 0.61)
  Top 0.305: v9.4,87.12 9.4,87.38 9.91,87.88 9.91,92.96 9.65,93.22 9.65,93.98 9.91,94.23 9.91,99.31 9.65,99.57 9.65,106.68 9.91,106.93 9.91,107.19 10.16,107.44 10.16,112.01 10.41,112.27 A24.J1 | v14.48,82.04 14.73,81.79 14.73,71.88 14.48,71.63 v14.48,68.33 | v35.05,68.33 v35.05,58.42
  2 0.305: v9.4,87.12 11.43,85.09 11.68,85.09 12.45,84.33 12.45,84.07 v14.48,82.04 | v35.05,58.42 35.56,58.42 49.78,44.2 49.78,43.43 B21.J1
  Bottom 0.305: B20.J2 54.86,42.93 49.78,42.93 B21.J1 | v14.48,68.33 14.73,68.58 34.8,68.58 v35.05,68.33
P_DATA05  (via drill 0.61)
  Top 0.305: v2.29,104.39 2.29,96.27 1.78,95.76 1.78,82.8 3.05,81.53 3.05,80.52 2.54,80.01 2.54,38.35 v2.79,38.1
  Bottom 0.305: B20.K2 58.17,39.62 55.63,39.62 53.85,37.85 50.55,37.85 B21.L1 48.51,36.58 47.24,36.58 44.96,38.86 42.16,38.86 41.15,37.85 38.1,37.85 37.85,38.1 35.05,38.1 34.8,37.85 31.75,37.85 31.5,38.1 28.7,38.1 28.45,37.85 25.4,37.85 25.15,38.1 22.35,38.1 22.1,37.85 19.05,37.85 18.8,38.1 16,38.1 15.75,37.85 12.7,37.85 12.45,38.1 9.65,38.1 9.4,37.85 6.35,37.85 6.1,38.1 v2.79,38.1 | v2.29,104.39 5.84,104.39 6.35,104.9 9.91,104.9 10.67,105.66 A24.L1
P_DATA06  (via drill 0.61)
  Top 0.305: v52.32,36.58 52.32,34.04 B21.M1 | v14.48,98.55 14.22,98.81 14.22,102.62 A24.M1 | v37.08,76.71 37.34,76.45 37.34,68.58 v37.08,68.33 | v54.1,68.58 54.36,68.33 54.36,62.48 54.1,62.23 54.1,42.42 55.12,41.4 55.12,40.39 54.86,40.13 54.86,36.83 B20.L2
  2 0.305: v14.48,98.55 20.83,92.2 21.59,92.2 v37.08,76.71
  Bottom 0.305: v52.32,36.58 54.86,36.58 B20.L2 | v37.08,68.33 53.85,68.33 v54.1,68.58
P_DATA07  (via drill 0.61)
  Top 0.305: v54.1,33.02 54.1,32 53.59,31.5 53.59,27.94 53.09,27.43 B21.P1 | v12.7,96.77 12.7,91.95 12.45,91.69 12.45,88.9 12.7,88.65 12.7,85.6 12.45,85.34 12.45,82.55 12.7,82.3 v12.7,76.71 | v29.21,76.96 29.72,76.45 29.72,71.12 29.97,70.87 29.97,67.06 v29.72,66.8 | v58.42,38.1 58.42,36.32 58.67,36.07 58.67,34.04 B20.M2
  2 0.305: v29.72,66.8 31.5,65.02 31.5,64.52 54.1,41.91 54.61,41.91 v58.42,38.1
  Bottom 0.305: v54.1,33.02 54.36,32.77 58.17,32.77 B20.M2 | v12.7,96.77 13.72,96.77 A24.P1 | v12.7,76.71 19.56,76.71 19.81,76.96 22.61,76.96 22.86,77.22 28.96,77.22 v29.21,76.96
P_DATA08  (via drill 0.61)
  Top 0.305: B21.S1 53.09,21.08 53.59,21.59 53.59,25.15 54.36,25.91 54.36,29.21 54.86,29.72 B20.N2 55.63,30.73 55.63,32.77 55.37,33.02 55.37,34.8 54.1,36.07 v54.1,40.89 | v18.8,90.42 18.8,88.9 19.05,88.65 19.05,85.6 18.8,85.34 18.8,82.55 19.05,82.3 v19.05,77.72 | v30.48,77.72 30.48,71.37 30.73,71.12 30.73,64.77 v30.48,64.52
  2 0.305: v54.1,40.89 v30.48,64.52
  Bottom 0.305: v18.8,90.42 14.99,90.42 A24.S1 | v19.05,77.72 22.35,77.72 22.61,77.98 30.23,77.98 v30.48,77.72
P_DATA09  (via drill 0.61)
  Top 0.305: v41.15,42.67 41.4,42.93 41.4,43.18 41.66,43.43 41.66,48.51 41.4,48.77 41.4,49.53 41.66,49.78 41.66,51.82 41.91,52.07 41.91,53.34 42.93,54.36 42.93,54.86 B21.D2 42.93,56.13 v42.93,58.42 | v2.79,125.48 2.79,116.59 3.05,116.33 3.05,115.32 2.54,114.81 2.54,107.19 v2.79,106.93 | v26.42,80.52 26.67,80.26 26.67,72.9 26.42,72.64 v26.42,67.31 | v36.83,64.52 v36.83,67.06
  2 0.305: v56.9,26.92 56.64,26.67 45.47,37.85 45.47,38.35 v41.15,42.67 | v3.3,103.38 22.86,83.82 22.86,83.57 23.88,82.55 24.38,82.55 v26.42,80.52 | v42.93,58.42 v36.83,64.52
  Bottom 0.305: v56.9,26.92 58.17,26.92 B20.P2 | v2.79,125.48 4.06,125.48 A24.D2 | v2.79,106.93 2.54,106.68 2.03,106.68 1.02,105.66 1.02,103.38 v3.3,103.38 | v26.42,67.31 26.92,67.82 34.04,67.82 34.8,67.06 v36.83,67.06
P_DATA10  (via drill 0.61)
  Top 0.305: v50.8,23.88 50.8,25.15 50.55,25.4 50.55,28.45 50.8,28.7 50.8,31.5 48.77,33.53 48.77,35.05 47.75,36.07 47.75,47.24 46.23,48.77 46.23,49.28 45.97,49.53 45.97,51.82 B21.E2 | v12.45,122.17 12.45,120.65 12.7,120.4 12.7,117.35 12.45,117.09 12.45,114.3 12.7,114.05 12.7,111 12.45,110.74 12.45,107.95 12.95,107.44 v12.95,104.9 | v40.89,82.3 40.89,67.06 41.4,66.55 v41.4,56.39
  15 0.305: v15.24,104.9 35.56,84.58 35.56,83.57 v36.58,82.55
  Bottom 0.305: v50.8,23.88 54.86,23.88 B20.R2 | v12.45,122.17 8.64,122.17 A24.E2 | v15.24,104.9 v12.95,104.9 | v36.58,82.55 37.85,82.55 38.1,82.3 v40.89,82.3 | v41.4,56.39 41.4,55.12 44.2,52.32 45.47,52.32 B21.E2
P_DATA11  (via drill 0.61)
  Top 0.305: v58.17,24.13 58.17,23.88 58.67,23.37 58.67,21.34 B20.S2 | v44.45,37.85 44.2,38.1 44.2,41.15 45.97,42.93 45.97,45.47 B21.H2 | v2.03,115.82 1.78,115.57 1.78,106.43 v2.54,105.66 | v27.18,82.04 27.43,81.79 27.43,72.64 27.18,72.39 27.18,68.07 28.7,66.55 v28.7,58.17
  2 0.305: v58.17,24.13 v44.45,37.85 | v2.54,105.66 6.1,102.11 6.1,101.6 22.61,85.09 24.38,85.09 25.15,84.33 25.15,84.07 v27.18,82.04
  15 0.305: v40.64,48.01 v30.48,58.17
  Bottom 0.305: v2.03,115.82 7.37,115.82 A24.H2 | v30.48,58.17 v28.7,58.17 | v40.64,48.01 42.67,45.97 45.47,45.97 B21.H2
P_DATAIN  (via drill 0.61)
  Top 0.305: v28.19,104.9 28.19,107.7 28.96,108.46 28.96,112.01 28.7,112.27 28.7,113.03 28.96,113.28 28.96,118.36 28.7,118.62 28.7,129.54 28.19,130.05 28.19,133.1 28.7,133.6 v28.7,136.91 | v95,120.65 95,123.7 95.25,123.95 v95.25,125.48 | v98.55,45.72 98.55,55.88 98.81,56.13 98.81,59.18 99.31,59.69 99.31,60.71 98.55,61.47 98.55,66.55 98.04,67.06 98.04,67.31 95.5,69.85 v95.5,88.14 | v88.65,96.52 88.65,98.3 88.9,98.55 88.9,101.35 87.88,102.36 87.88,103.89 88.9,104.9 88.9,107.7 88.65,107.95 88.65,111 88.9,111.25 88.9,114.05 88.65,114.3 88.65,117.35 89.15,117.86 89.15,119.63 v89.41,119.89
  2 0.305: v98.55,45.72 98.55,44.7 97.28,43.43 97.28,40.39 B17.K2 | v95.5,88.14 95.5,88.39 93.73,90.17 93.73,90.93 92.96,91.69 91.44,91.69 89.92,93.22 89.92,93.98 88.65,95.25 v88.65,96.52
  15 0.305: v70.36,137.92 71.88,137.92 75.95,133.86 75.95,133.35 v89.41,119.89
  Bottom 0.305: v28.19,104.9 25.65,104.9 25.15,104.39 21.59,104.39 21.08,103.89 A23.M2 | v28.7,136.91 28.96,137.16 43.69,137.16 43.94,137.41 48.77,137.41 49.02,137.67 55.37,137.67 55.88,138.18 70.1,138.18 v70.36,137.92 | v89.41,119.89 89.66,120.14 91.44,120.14 91.95,120.65 v95,120.65 | v95.25,125.48 99.31,125.48 A17.D1
P_EXTA0  (via drill 0.61)
  Top 0.305: v2.03,81.03 1.78,80.77 1.78,6.1 v2.03,5.84 | v33.78,5.59 v33.78,2.03 | v95.25,2.03 95.25,12.45 95,12.7 95,15.75 96.77,17.53 96.77,20.07 B17.S2 96.77,21.34 96.77,23.62 95,25.4 95,28.19 95.25,28.45 95.25,31.5 95,31.75 95,34.54 v97.28,36.83 | v107.7,96.52 107.7,95.25 107.95,95 107.95,91.95 107.7,91.69 107.7,88.9 107.95,88.65 107.95,85.6 107.7,85.34 107.7,82.55 108.97,81.28 108.97,79.25 108.46,78.74 108.46,69.6 111.25,66.8 v111.25,44.45 | v101.6,39.37 v101.6,43.69
  2 0.305: v97.28,36.83 v99.57,39.12
  Bottom 0.305: v2.03,81.03 4.06,81.03 A24.V2 | v2.03,5.84 2.54,5.33 31.75,5.33 32,5.59 v33.78,5.59 | v33.78,2.03 34.04,1.78 95,1.78 v95.25,2.03 | v107.7,96.52 106.17,96.52 105.92,96.77 103.89,96.77 A17.P1 | v111.25,44.45 111,44.2 107.95,44.2 107.7,44.45 105.16,44.45 104.39,43.69 v101.6,43.69 | v101.6,39.37 101.35,39.12 v99.57,39.12
P_EXTA1  (via drill 0.61)
  Top 0.305: v4.83,82.55 4.83,86.61 A24.T2 | v7.37,78.99 v7.37,82.3 | v3.56,78.99 3.3,78.74 3.3,39.12 3.81,38.61 3.81,37.59 2.54,36.32 2.54,7.11 v3.3,6.35 | v91.69,8.13 91.69,12.45 92.2,12.95 92.2,17.78 92.46,18.03 92.46,19.56 93.73,20.83 93.73,23.11 B17.R2 | v114.3,94.49 114.3,91.95 114.05,91.69 114.05,88.9 114.3,88.65 114.3,85.6 114.05,85.34 114.05,82.55 114.3,82.3 114.3,72.64 113.03,71.37 113.03,70.36 113.28,70.1 113.28,64.77 v113.03,64.52 | v115.32,62.23 115.06,61.98 115.06,60.2 114.05,59.18 114.05,57.15 114.3,56.9 114.3,53.85 114.05,53.59 114.05,50.8 114.3,50.55 114.3,47.5 114.05,47.24 114.05,44.45 114.3,44.2 v114.3,40.89 | v111.25,40.89 111.25,29.72 111.51,29.46 111.51,28.45 112.27,27.69 v112.27,25.4 | v108.97,23.37 v108.97,25.15
  2 0.305: v106.68,102.87 106.68,102.62 114.3,95 v114.3,94.49 | v115.32,62.23 v113.03,64.52 | v108.97,23.37 107.44,21.84 104.65,21.84 104.14,22.35 v102.87,22.35
  Bottom 0.305: v4.83,82.55 6.1,82.55 6.35,82.3 v7.37,82.3 | v3.56,78.99 v7.37,78.99 | v3.3,6.35 3.56,6.1 31.5,6.1 31.75,6.35 33.02,6.35 34.8,8.13 43.43,8.13 43.69,8.38 69.09,8.38 69.34,8.13 v91.69,8.13 | v106.68,102.87 106.17,102.87 105.92,103.12 103.89,103.12 A17.M1 | v111.25,40.89 v114.3,40.89 | v112.27,25.4 111,25.4 110.74,25.15 v108.97,25.15 | v102.87,22.35 99.57,22.35 98.55,23.37 97.54,23.37 97.28,23.11 93.98,23.11 B17.R2
P_EXTA2  (via drill 0.61)
  Top 0.305: v2.79,90.42 2.54,90.68 2.54,95.5 3.05,96.01 3.05,97.79 v3.3,98.04 | v1.27,98.04 1.02,98.3 1.02,143 v1.27,143.26 | v42.93,143.26 v42.93,138.94 | v98.55,139.19 98.55,124.97 98.81,124.71 98.81,119.63 98.55,119.38 98.55,112.27 99.82,111 99.82,109.98 100.08,109.73 100.08,106.93 A17.L1 | v9.14,69.34 9.14,82.3 9.65,82.8 9.65,85.34 7.87,87.12 7.87,89.92 A24.S2
  15 0.305: v92.71,27.69 69.34,51.05 69.34,51.56 52.58,68.33 v52.58,69.34
  Bottom 0.305: v2.79,90.42 7.37,90.42 A24.S2 | v3.3,98.04 v1.27,98.04 | v1.27,143.26 1.52,143.51 42.67,143.51 v42.93,143.26 | v42.93,138.94 48.26,138.94 48.51,139.19 54.86,139.19 55.37,139.7 90.68,139.7 91.19,139.19 v98.55,139.19 | v92.71,27.69 92.96,27.94 96.27,27.94 96.52,27.69 B17.P2 | v52.58,69.34 52.32,69.09 37.85,69.09 37.59,69.34 v9.14,69.34
P_INIT  (via drill 0.61)
  Top 0.305: v70.1,77.98 70.1,84.84 70.61,85.34 70.61,88.65 70.87,88.9 70.87,89.92 A19.S2 | v55.63,77.98 55.63,80.26 A20.V2
  Bottom 0.305: A20.V2 54.86,81.03 51.31,81.03 49.78,79.5 23.37,79.5 21.84,81.03 18.03,81.03 A23.V2 | v55.63,77.98 v70.1,77.98
P_IOP1  (via drill 0.61)
  Top 0.305: v60.45,130.05 60.45,124.97 60.71,124.71 60.71,119.63 60.45,119.38 60.45,114.55 59.94,114.05 59.94,110.49 59.44,109.98 A20.K2
  15 0.305: v72.9,130.05 v77.47,125.48
  Bottom 0.305: v60.45,130.05 60.71,129.79 63.25,129.79 63.75,130.3 66.04,130.3 66.55,129.79 69.6,129.79 70.1,130.3 72.64,130.3 v72.9,130.05 | v77.47,125.48 80.26,125.48 A18.D2
P_IOP2  (via drill 0.61)
  Top 0.305: v63.25,103.63 63.25,104.65 63.5,104.9 v63.5,105.66 | v66.29,105.66 66.29,107.7 66.8,108.2 v66.8,109.73 | v69.6,109.73 69.6,111 69.85,111.25 v69.85,113.54 | v73.15,113.54 73.66,114.05 v73.66,115.57
  15 0.305: v73.66,115.57 v79.76,109.47
  Bottom 0.305: v63.25,103.63 62.99,103.89 59.18,103.89 A20.M2 | v63.5,105.66 v66.29,105.66 | v66.8,109.73 v69.6,109.73 | v69.85,113.54 v73.15,113.54 | v79.76,109.47 83.57,109.47 A18.K2
P_IOP4  (via drill 0.61)
  15 0.305: v72.64,98.55 72.9,98.55 v81.03,90.42
  Bottom 0.305: v72.64,98.55 63.75,98.55 63.25,98.04 59.69,98.04 59.18,97.54 A20.P2 | v81.03,90.42 83.57,90.42 A18.S2
P_IRQ  (via drill 0.61)
  Top 0.305: v91.69,35.56 91.69,37.85 92.2,38.35 v92.2,39.12 | v95,39.12 95,41.15 95.25,41.4 95.25,44.2 95,44.45 95,46.23 96.52,47.75 96.52,49.28 96.77,49.53 96.77,51.82 B17.E2
  2 0.305: v36.83,103.12 36.83,102.62 40.13,99.31 40.89,99.31 59.44,80.77 59.94,80.77 60.71,80.01 v60.71,79.76
  15 0.305: v64.77,79.76 77.72,66.8 79.25,66.8 87.88,58.17 88.14,58.17 88.65,57.66 88.65,57.4 92.46,53.59 95.5,53.59 96.27,52.83 B17.E2
  Bottom 0.305: v91.69,35.56 91.44,35.56 90.93,35.05 89.15,35.05 88.65,34.54 85.09,34.54 84.58,34.04 B18.M2 | v92.2,39.12 v95,39.12 | v36.83,103.12 34.04,103.12 A22.M2 | v60.71,79.76 61.21,79.76 61.47,79.5 64.52,79.5 v64.77,79.76
P_LINE  (via drill 0.61)
  Top 0.305: v98.04,22.35 98.04,25.15 98.55,25.65 98.55,40.89 97.03,42.42 97.03,42.93 96.77,43.18 96.77,45.47 B17.H2 | v82.55,25.4 84.07,23.88 84.07,21.34 B18.S2
  2 0.305: v82.55,25.4 53.59,54.36 53.59,54.61 50.55,57.66 50.55,58.67 44.2,65.02 44.2,66.55 30.48,80.26 A22.V2
  Bottom 0.305: v98.04,22.35 89.15,22.35 88.65,21.84 85.09,21.84 84.58,21.34 B18.S2
P_MB00  (via drill 0.61)
  Top 0.305: v158.5,139.7 158.5,133.35 158.75,133.1 158.75,130.3 157.23,128.78 157.23,125.98 A12.D2 | v125.48,139.95 125.48,132.33 A15.B1
  Bottom 0.305: A15.B1 124.71,131.83 120.9,131.83 119.63,133.1 54.86,133.1 53.59,131.83 49.78,131.83 A21.B1 | v158.5,139.7 125.73,139.7 v125.48,139.95
P_MB01  (via drill 0.61)
  Top 0.305: v152.4,119.13 152.4,120.4 152.15,120.65 v152.15,123.44
  Bottom 0.305: A21.D1 49.78,125.48 52.58,125.48 53.85,126.75 120.14,126.75 121.41,125.48 124.71,125.48 A15.D1 125.98,125.48 128.52,125.48 130.3,127.25 138.43,127.25 140.21,125.48 142.49,125.48 144.02,123.95 148.84,123.95 149.35,123.44 v152.15,123.44 | v152.4,119.13 156.46,119.13 A12.F2
P_MB02  (via drill 0.61)
  Top 0.305: v131.57,114.3 131.32,114.55 v131.32,116.33 | v128.52,119.13 128.52,121.67 A15.E1 128.52,122.94 128.52,126.75 127.25,128.02 127.25,132.84 126.24,133.86 126.24,139.19 126.49,139.45 v126.49,141.22 | v54.1,140.97 54.1,133.6 53.59,133.1 53.59,130.05 54.1,129.54 54.1,127.25 53.59,126.75 53.59,123.19 53.09,122.68 A21.E1
  2 0.305: v128.52,119.13 v131.32,116.33
  Bottom 0.305: v131.57,114.3 133.1,114.3 133.35,114.05 136.14,114.05 136.4,114.3 139.45,114.3 139.7,114.05 142.49,114.05 142.75,114.3 145.8,114.3 146.05,114.05 148.84,114.05 149.1,114.3 152.15,114.3 153.67,112.78 156.46,112.78 A12.J2 | v54.1,140.97 54.36,141.22 91.19,141.22 91.69,140.72 92.71,140.72 93.98,141.99 116.33,141.99 116.84,141.48 119.63,141.48 119.89,141.22 v126.49,141.22
P_MB03  (via drill 0.61)
  Top 0.305: v144.02,101.6 v144.02,103.38
  15 0.305: v144.02,103.38 v136.14,111.25
  Bottom 0.305: A21.J1 49.78,112.78 52.58,112.78 54.1,111.25 119.89,111.25 121.41,112.78 124.71,112.78 A15.J1 125.98,112.78 129.79,112.78 131.32,111.25 v136.14,111.25 | v144.02,101.6 145.8,101.6 146.05,101.35 148.84,101.35 149.1,101.6 152.15,101.6 153.67,100.08 156.46,100.08 A12.N2
P_MB03\  (via drill 0.61)
  Top 0.305: v130.3,108.97 130.3,110.49 129.79,111 129.79,112.27 129.03,113.03 129.03,115.32 A15.H1 128.52,116.59 128.52,117.6 127.51,118.62 127.51,119.89 126.75,120.65 126.75,123.44 127,123.7 127,126.75 126.75,127 126.75,127.51 126.49,127.76 126.49,128.78 123.95,131.32 v123.95,140.21 | v47.24,123.7 47.24,126.75 47.75,127.25 v47.75,139.95
  2 0.305: v47.24,123.7 52.83,118.11 52.83,116.59 A21.H1
  Bottom 0.305: v130.3,108.97 132.33,108.97 133.6,107.7 136.14,107.7 136.4,107.95 139.45,107.95 139.7,107.7 142.49,107.7 142.75,107.95 145.8,107.95 146.05,107.7 148.84,107.7 149.1,107.95 152.15,107.95 153.67,106.43 156.46,106.43 A12.L2 | v47.75,139.95 54.61,139.95 55.12,140.46 90.93,140.46 91.44,139.95 92.96,139.95 94.23,141.22 116.08,141.22 116.59,140.72 119.38,140.72 119.63,140.46 123.7,140.46 v123.95,140.21
P_MB04  (via drill 0.61)
  Top 0.305: v144.53,120.65 144.53,124.71 A13.D2 | v133.35,120.4 133.35,117.35 133.1,117.09 133.1,114.3 133.35,114.05 133.35,111 133.1,110.74 133.1,107.95 133.35,107.7 133.35,104.65 133.1,104.39 v133.1,103.38
  Bottom 0.305: A21.M1 53.09,103.12 55.88,103.12 57.15,101.85 123.44,101.85 124.71,103.12 128.02,103.12 A15.M1 129.29,103.12 131.32,103.12 131.57,103.38 v133.1,103.38 | v144.53,120.65 142.75,120.65 142.49,120.4 139.7,120.4 139.45,120.65 136.4,120.65 136.14,120.4 v133.35,120.4
P_MB04\  (via drill 0.61)
  Top 0.305: v50.55,142.49 50.55,133.35 50.8,133.1 50.8,130.3 50.55,130.05 50.55,127 50.8,126.75 50.8,123.95 50.55,123.7 50.55,120.65 50.8,120.4 50.8,117.6 50.55,117.35 50.55,114.3 50.8,114.05 50.8,111.25 49.28,109.73 49.28,106.93 A21.L1 | v120.4,142.24 120.4,133.35 120.65,133.1 120.65,130.05 120.4,129.79 120.4,127 120.65,126.75 120.65,123.7 120.4,123.44 120.4,120.65 120.65,120.4 120.65,117.35 120.4,117.09 120.4,114.3 120.65,114.05 120.65,111 120.4,110.74 120.4,107.95 120.65,107.7 v120.65,106.43 | v152.4,93.73 152.4,95 152.15,95.25 152.15,98.3 152.4,98.55 152.4,101.35 152.15,101.6 v152.15,104.39
  Bottom 0.305: v50.55,142.49 50.8,142.75 116.59,142.75 117.09,142.24 v120.4,142.24 | v120.65,106.43 124.71,106.43 A15.L1 125.98,106.43 129.79,106.43 131.32,104.9 148.84,104.9 149.35,104.39 v152.15,104.39 | v152.4,93.73 156.46,93.73 A12.R2
P_MB05  (via drill 0.61)
  Top 0.305: v143,95.25 143,106.68 143.26,106.93 143.26,107.19 143.51,107.44 143.51,112.01 143.76,112.27 A13.J2 | v128.52,95 128.52,91.19 A15.S1
  Bottom 0.305: A15.S1 128.02,90.42 124.71,90.42 123.44,89.15 57.15,89.15 55.88,90.42 53.09,90.42 A21.S1 | v143,95.25 142.75,95 139.7,95 139.45,95.25 136.4,95.25 136.14,95 133.35,95 133.1,95.25 130.05,95.25 129.79,95 v128.52,95
P_MB05\  (via drill 0.61)
  Top 0.305: v139.7,119.13 139.7,117.35 139.45,117.09 139.45,114.3 139.7,114.05 139.7,111 139.45,110.74 139.45,107.95 139.7,107.7 139.7,104.65 139.45,104.39 v139.45,101.6 | v129.54,101.35 129.54,97.54 129.29,97.28 A15.P1
  Bottom 0.305: A15.P1 128.02,96.77 124.71,96.77 123.44,95.5 57.15,95.5 55.88,96.77 53.09,96.77 A21.P1 | v139.7,119.13 143.76,119.13 A13.F2 | v139.45,101.6 136.4,101.6 136.14,101.35 133.35,101.35 133.1,101.6 130.05,101.6 129.79,101.35 v129.54,101.35
P_MB06  (via drill 0.61)
  Top 0.305: v140.97,101.6 v140.97,100.08 | v121.92,120.65 122.17,120.65 122.17,121.67 A15.E2
  2 0.305: v121.92,120.65 v140.97,101.6
  Bottom 0.305: A15.E2 121.67,122.17 117.86,122.17 116.33,123.7 51.05,123.7 49.53,122.17 46.74,122.17 A21.E2 | v140.97,100.08 143.76,100.08 A13.N2
P_MB06\  (via drill 0.61)
  Top 0.305: v44.2,143.26 44.2,133.35 44.45,133.1 44.45,130.3 42.93,128.78 42.93,125.98 A21.D2 | v117.6,143.26 117.6,131.32 119.13,129.79 119.13,125.98 A15.D2 | v144.53,110.74 144.53,106.93 A13.L2
  15 0.305: v131.83,123.44 v144.53,110.74
  Bottom 0.305: v44.2,143.26 44.45,143.51 117.35,143.51 v117.6,143.26 | v131.83,123.44 130.3,123.44 129.79,123.95 124.97,123.95 124.21,124.71 119.38,124.71 A15.D2
P_MB07  (via drill 0.61)
  Top 0.305: v130.3,114.3 130.3,119.38 130.56,119.63 130.56,119.89 130.81,120.14 130.81,124.71 131.06,124.97 A14.D2 | v122.43,114.05 122.43,112.52 122.17,112.27 122.17,110.24 A15.K2
  Bottom 0.305: A15.K2 121.67,109.47 117.86,109.47 116.59,108.2 50.8,108.2 49.53,109.47 46.74,109.47 A21.K2 | v130.3,114.3 130.05,114.05 127,114.05 126.75,114.3 123.7,114.3 123.44,114.05 v122.43,114.05
P_MB07\  (via drill 0.61)
  15 0.305: v140.97,93.98 128.02,106.93 128.02,108.2 123.44,112.78 123.44,114.05 123.7,114.3 122.68,115.32 A15.H2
